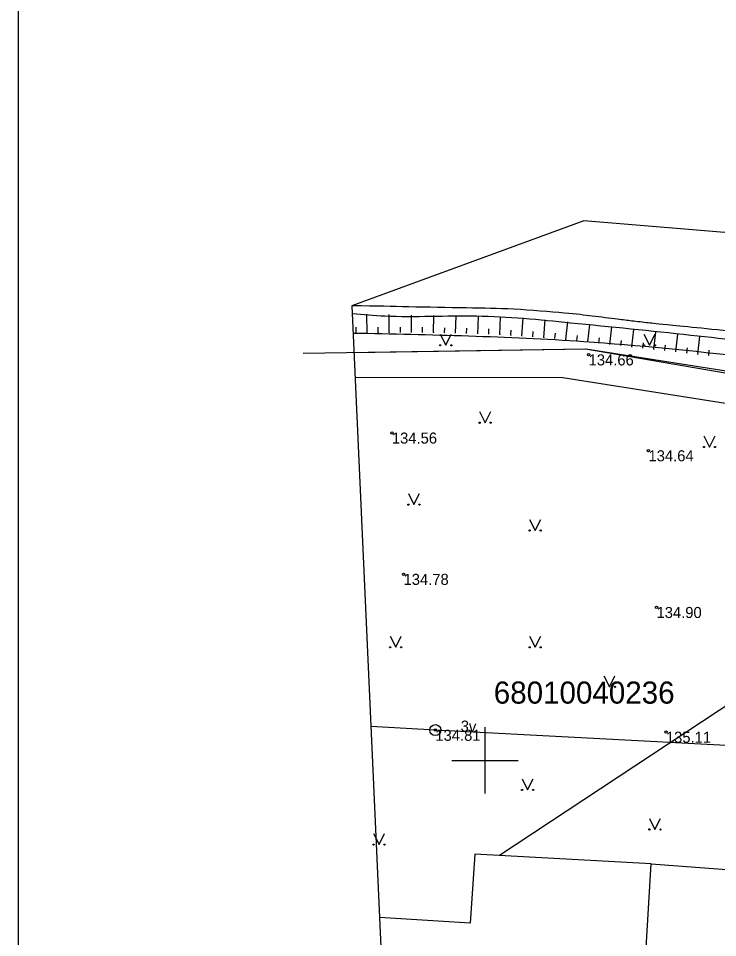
# Model space of a CAD drawing. Extents: x 728710 to 728960, y 272811 to 273475.
# Drawn here: x 728728.89 to 728760.53, y 273391.98 to 273433.56 of the extents above; entities that cross this region are included whole.
import ezdxf

# ---------------------------------------------------------------- set-up
doc = ezdxf.new("R2010")
doc.units = 0
for name, color, linetype in [('Level 10', 7, 'Continuous'), ('Level 12', 7, 'Continuous'), ('Level 15', 7, 'Continuous'), ('Level 21', 7, 'Continuous'), ('Level 23', 7, 'Continuous'), ('Level 3', 7, 'Continuous'), ('Level 33', 7, 'Continuous'), ('Level 34', 7, 'Continuous'), ('Level 35', 7, 'Continuous'), ('Level 42', 7, 'Continuous'), ('Level 48', 7, 'Continuous'), ('Level 53', 7, 'Continuous'), ('Level 57', 7, 'Continuous'), ('RAMI_PLAN_####_TKST_#', 7, 'Continuous'), ('RAMI_UZMR_####_####_#', 7, 'Continuous'), ('ROBZ_KADS_####_TKST_#', 7, 'Continuous'), ('ROBZ_UZMR_####_####_#', 7, 'Continuous'), ('TERT_KONT_####_####_#', 7, 'Continuous')]:
    doc.layers.add(name, color=color, linetype=linetype)

msp = doc.modelspace()

# ---------------------------------------------------------------- linework, layer by layer
at = {"layer": 'Level 10'}
for p, q in [((728750, 273401.5), (728750, 273400)), ((728748.5, 273400), (728750, 273400)), ((728750, 273400), (728750, 273398.5)), ((728750, 273400), (728751.5, 273400))]:
    msp.add_line(p, q, dxfattribs=at)
at = {"layer": 'Level 12'}
for p, q in [((728744.673, 273419.338), (728744.661, 273420.178)), ((728745.673, 273419.352), (728745.662, 273420.157)), ((728746.673, 273419.355), (728746.671, 273420.135)), ((728747.673, 273419.347), (728747.68, 273420.114)), ((728748.672, 273419.325), (728748.691, 273420.092)), ((728749.672, 273419.296), (728749.706, 273420.07)), ((728750.671, 273419.252), (728750.705, 273420.043)), ((728751.669, 273419.194), (728751.731, 273419.994)), ((728752.666, 273419.117), (728752.729, 273419.928)), ((728753.662, 273419.026), (728753.743, 273419.831)), ((728744.173, 273419.328), (728744.166, 273419.585)), ((728745.173, 273419.345), (728745.169, 273419.592)), ((728745.173, 273419.345), (728745.173, 273419.342)), ((728745.673, 273419.352), (728745.673, 273419.342)), ((728746.173, 273419.354), (728746.172, 273419.591)), ((728746.173, 273419.354), (728746.173, 273419.351)), ((728746.673, 273419.355), (728746.673, 273419.345)), ((728747.173, 273419.352), (728747.175, 273419.584)), ((728747.173, 273419.352), (728747.173, 273419.349)), ((728747.673, 273419.347), (728747.672, 273419.337)), ((728748.172, 273419.337), (728748.178, 273419.567)), ((728749.172, 273419.312), (728749.178, 273419.543)), ((728750.171, 273419.274), (728750.182, 273419.51)), ((728751.17, 273419.223), (728751.184, 273419.463)), ((728752.168, 273419.155), (728752.186, 273419.398)), ((728754.657, 273418.925), (728754.746, 273419.719)), ((728755.651, 273418.813), (728755.739, 273419.6)), ((728756.644, 273418.702), (728756.732, 273419.48)), ((728757.638, 273418.59), (728757.726, 273419.371)), ((728744.173, 273419.328), (728744.173, 273419.325)), ((728744.673, 273419.338), (728744.673, 273419.328)), ((728748.172, 273419.337), (728748.172, 273419.334)), ((728748.672, 273419.325), (728748.672, 273419.315)), ((728749.172, 273419.312), (728749.172, 273419.309)), ((728749.672, 273419.296), (728749.671, 273419.286)), ((728750.171, 273419.274), (728750.171, 273419.271)), ((728750.671, 273419.252), (728750.67, 273419.242)), ((728751.17, 273419.223), (728751.17, 273419.22)), ((728751.669, 273419.194), (728751.668, 273419.184)), ((728752.168, 273419.155), (728752.167, 273419.152)), ((728752.666, 273419.117), (728752.665, 273419.107)), ((728753.165, 273419.076), (728753.164, 273419.073)), ((728753.165, 273419.076), (728753.189, 273419.318)), ((728753.662, 273419.026), (728753.661, 273419.016)), ((728754.16, 273418.977), (728754.159, 273418.974)), ((728754.16, 273418.977), (728754.184, 273419.217)), ((728755.154, 273418.869), (728755.18, 273419.106)), ((728756.148, 273418.757), (728756.174, 273418.992)), ((728758.632, 273418.479), (728758.721, 273419.269)), ((728759.626, 273418.368), (728759.716, 273419.169)), ((728754.657, 273418.925), (728754.656, 273418.915)), ((728755.154, 273418.869), (728755.153, 273418.866)), ((728755.651, 273418.813), (728755.65, 273418.803)), ((728756.148, 273418.757), (728756.147, 273418.755)), ((728756.644, 273418.702), (728756.643, 273418.692)), ((728757.141, 273418.646), (728757.168, 273418.88)), ((728757.141, 273418.646), (728757.141, 273418.643)), ((728757.638, 273418.59), (728757.637, 273418.58)), ((728758.135, 273418.535), (728758.161, 273418.77)), ((728758.135, 273418.535), (728758.135, 273418.532)), ((728759.129, 273418.423), (728759.156, 273418.662)), ((728760.123, 273418.312), (728760.15, 273418.554)), ((728758.632, 273418.479), (728758.631, 273418.469)), ((728759.129, 273418.423), (728759.129, 273418.42)), ((728759.626, 273418.368), (728759.625, 273418.358)), ((728760.123, 273418.312), (728760.122, 273418.309))]:
    msp.add_line(p, q, dxfattribs=at)
msp.add_spline([(728744.037, 273419.326), (728754.471, 273418.946), (728769.216, 273417.292)], degree=3, dxfattribs=at)
at = {"layer": 'Level 15'}
msp.add_circle((728747.755, 273401.369), 0.25, dxfattribs=at)
at = {"layer": 'Level 21'}
for p, q in [((728747.755, 273401.368), (728744.84, 273401.533)), ((728764.632, 273400.484), (728747.755, 273401.368))]:
    msp.add_line(p, q, dxfattribs=at)
at = {"layer": 'Level 23'}
msp.add_lwpolyline([(728775.104, 273411.821), (728750.664, 273395.692)], dxfattribs=at)
at = {"layer": 'Level 3'}
for p, q in [((728749.538, 273395.754), (728749.332, 273392.642)), ((728757.526, 273395.316), (728749.538, 273395.754)), ((728757.036, 273387.45), (728757.526, 273395.316)), ((728749.332, 273392.642), (728745.23, 273392.888))]:
    msp.add_line(p, q, dxfattribs=at)
at = {"layer": 'Level 33'}
msp.add_open_spline([(728769.065, 273418.557), (728765.53, 273418.968), (728761.943, 273419.325), (728757.907, 273419.728), (728757.462, 273419.774), (728756.571, 273419.878), (728756.124, 273419.934), (728754.781, 273420.101), (728753.88, 273420.212), (728751.16, 273420.436), (728749.348, 273420.453), (728746.359, 273420.511), (728745.171, 273420.54), (728743.982, 273420.563)], degree=3, dxfattribs=at)
at = {"layer": 'Level 34'}
msp.add_spline([(728803.711, 273405.484), (728801.422, 273405.484), (728800.253, 273405.69), (728798.991, 273406.049), (728798.257, 273406.395), (728798.035, 273406.78), (728799.137, 273408.348), (728800.771, 273410.635), (728801.169, 273411.645), (728801.395, 273412.814), (728801.395, 273413.639), (728800.811, 273414.542), (728800.187, 273415.101), (728799.098, 273415.433), (728798.208, 273415.433), (728796.959, 273415.154), (728795.698, 273414.702), (728794.542, 273414.463), (728793.32, 273414.463), (728792.63, 273414.463), (728791.78, 273415.127), (728789.217, 273417.32), (728787.889, 273418.277), (728786.202, 273418.969), (728783.997, 273419.181), (728781.062, 273419.181), (728779.402, 273419.048), (728774.594, 273418.875), (728772.615, 273418.556), (728768.674, 273418.296), (728764.235, 273418.663), (728759.321, 273419.221), (728753.876, 273419.779), (728749.613, 273420.085), (728745.469, 273420.085), (728743.998, 273420.191)], degree=3, dxfattribs=at)
at = {"layer": 'Level 35'}
for points in [[(728744.077, 273418.442), (728754.56, 273418.606), (728771.59, 273415.937)], [(728757.526, 273395.316), (728772.98, 273394.153)]]:
    msp.add_lwpolyline(points, dxfattribs=at)
at = {"layer": 'Level 42'}
msp.add_lwpolyline([(728744.127, 273417.336), (728753.529, 273417.32), (728763.941, 273415.674), (728771.995, 273414.301), (728772.789, 273413.658), (728772.866, 273409.228), (728774.333, 273393.944), (728774.498, 273390.902), (728774.316, 273388.778), (728772.706, 273388.348), (728772.062, 273387.726), (728772.188, 273385.974), (728773.233, 273385.001), (728774.349, 273385.73), (728774.847, 273385.541), (728775.23, 273379.296), (728776.795, 273371.75), (728778.361, 273363.303)], dxfattribs=at)
at = {"layer": 'Level 48'}
for centre in [(728754.688, 273418.346), (728745.787, 273414.811), (728757.397, 273414.009), (728746.316, 273408.42), (728757.761, 273406.924), (728747.755, 273401.368), (728758.184, 273401.281)]:
    msp.add_circle(centre, 0.0534, dxfattribs=at)
at = {"layer": 'RAMI_PLAN_####_TKST_#'}
msp.add_lwpolyline([(728728.89, 273202.048), (728728.89, 273475.126), (728912.915, 273475.126), (728912.915, 273202.048)], close=True, dxfattribs=at)
at = {"layer": 'RAMI_UZMR_####_####_#'}
msp.add_lwpolyline([(728810.773, 273260.978), (728802.611, 273315.901), (728795.796, 273348.362), (728794.274, 273357.438), (728805.771, 273362.009), (728805.234, 273373.998), (728803.936, 273379.727), (728791.234, 273379.578), (728787.734, 273403.429), (728803.558, 273404.599), (728803.908, 273418.239), (728787.419, 273421.679), (728754.475, 273424.404), (728743.982, 273420.563), (728745.23, 273392.888), (728745.879, 273378.489), (728747.149, 273361.103), (728773.116, 273356.557), (728775.22, 273317.659), (728767.872, 273315.668), (728768.286, 273308.258), (728775.846, 273306.093), (728776.746, 273299.712), (728774.767, 273288.109)], dxfattribs=at)
at = {"layer": 'ROBZ_UZMR_####_####_#'}
for p, q in [((728754.544, 273418.603), (728741.771, 273418.405)), ((728771.692, 273415.636), (728754.544, 273418.603))]:
    msp.add_line(p, q, dxfattribs=at)
at = {"layer": 'TERT_KONT_####_####_#'}
for p, q in [((728747.976, 273419.271), (728748.226, 273418.771)), ((728748.226, 273418.771), (728748.476, 273419.271)), ((728757.194, 273419.271), (728757.444, 273418.771)), ((728757.444, 273418.771), (728757.694, 273419.271)), ((728749.759, 273415.771), (728750.009, 273415.271)), ((728750.009, 273415.271), (728750.259, 273415.771)), ((728759.908, 273414.671), (728760.158, 273414.171)), ((728760.158, 273414.171), (728760.408, 273414.671)), ((728746.536, 273412.065), (728746.786, 273411.565)), ((728746.786, 273411.565), (728747.036, 273412.065)), ((728752.022, 273410.898), (728752.272, 273410.398)), ((728752.272, 273410.398), (728752.522, 273410.898)), ((728745.713, 273405.613), (728745.963, 273405.113)), ((728745.963, 273405.113), (728746.213, 273405.613)), ((728752.022, 273405.613), (728752.272, 273405.113)), ((728752.272, 273405.113), (728752.522, 273405.613)), ((728755.382, 273403.829), (728755.632, 273403.329)), ((728755.632, 273403.329), (728755.882, 273403.829)), ((728751.679, 273399.162), (728751.929, 273398.662)), ((728751.929, 273398.662), (728752.179, 273399.162)), ((728757.439, 273397.377), (728757.689, 273396.877)), ((728757.689, 273396.877), (728757.939, 273397.377)), ((728744.958, 273396.691), (728745.208, 273396.191)), ((728745.208, 273396.191), (728745.458, 273396.691))]:
    msp.add_line(p, q, dxfattribs=at)
for centre, radius in [((728747.975, 273418.771), 0.028), ((728748.475, 273418.771), 0.0263), ((728757.194, 273418.771), 0.028), ((728757.694, 273418.771), 0.0263), ((728749.758, 273415.27), 0.028), ((728750.258, 273415.27), 0.0263), ((728759.908, 273414.17), 0.028), ((728760.408, 273414.17), 0.0263), ((728746.535, 273411.564), 0.028), ((728747.035, 273411.564), 0.0263), ((728752.021, 273410.397), 0.028), ((728752.521, 273410.397), 0.0263), ((728745.712, 273405.113), 0.028), ((728746.212, 273405.113), 0.0263), ((728752.021, 273405.113), 0.028), ((728752.521, 273405.113), 0.0263), ((728755.382, 273403.328), 0.028), ((728755.882, 273403.328), 0.0263), ((728751.679, 273398.661), 0.028), ((728752.179, 273398.661), 0.0263), ((728757.439, 273396.877), 0.028), ((728757.939, 273396.877), 0.0263), ((728744.958, 273396.19), 0.028), ((728745.458, 273396.19), 0.0263)]:
    msp.add_circle(centre, radius, dxfattribs=at)

# ---------------------------------------------------------------- texts
at = {"layer": 'Level 53'}
msp.add_text('3v', height=0.5, rotation=357.0001, dxfattribs=at).set_placement((728748.888, 273401.309))
at = {"layer": 'Level 57'}
for s, p in [('134.66', (728754.688, 273417.861)), ('134.56', (728745.787, 273414.326)), ('134.64', (728757.397, 273413.524)), ('134.78', (728746.316, 273407.936)), ('134.90', (728757.761, 273406.438)), ('134.81', (728747.755, 273400.884)), ('135.11', (728758.184, 273400.795))]:
    msp.add_text(s, height=0.5, dxfattribs=at).set_placement(p)
at = {"layer": 'ROBZ_KADS_####_TKST_#'}
msp.add_text('68010040236', height=1, dxfattribs=at).set_placement((728750.398, 273402.566))

doc.saveas('drawing.dxf')
